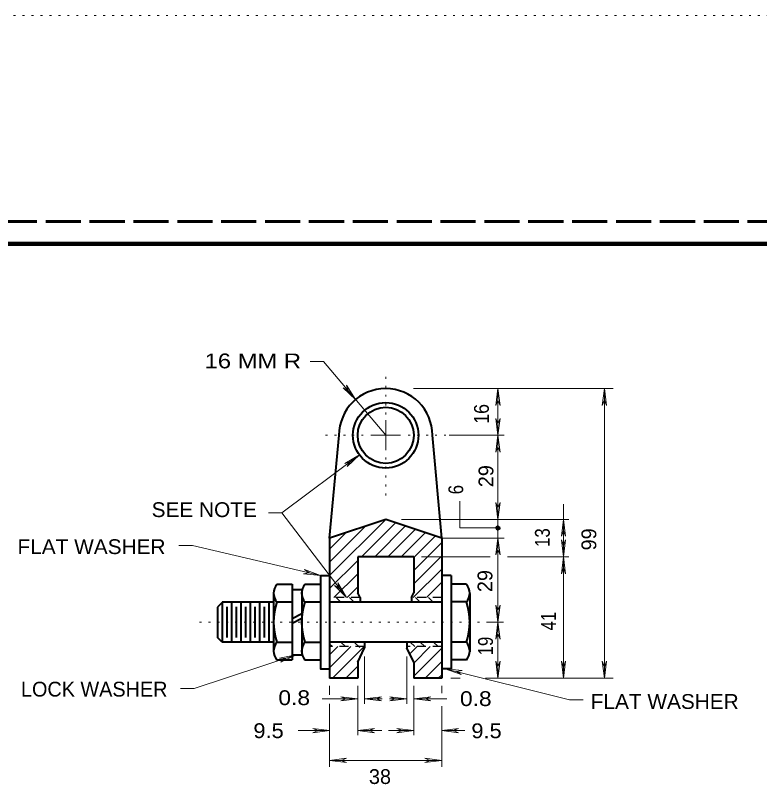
# Model space of a CAD drawing. Extents: x 312583 to 312854, y 144419 to 144597.
# Drawn here: x 312686.4 to 312724.55, y 144556.8 to 144596.78 of the extents above; entities that cross this region are included whole.
import ezdxf

# ---------------------------------------------------------------- set-up
doc = ezdxf.new("R2010")
doc.units = 0
doc.header["$LTSCALE"] = 0.3
for name, pattern in [('DOTTED', [1.5, 0.3, -1.2]), ('LONG_DASHED', [7.5, 6, -1.5]), ('SHORT_DASHED', [2.7, 1.5, -1.2])]:
    doc.linetypes.add(name, pattern=pattern)
for name, color, linetype, lineweight in [('1', 7, 'Continuous', 40), ('2', 7, 'Continuous', 13), ('62', 7, 'DOTTED', 13), ('63', 7, 'LONG_DASHED', 60)]:
    doc.layers.add(name, color=color, linetype=linetype, lineweight=lineweight)

msp = doc.modelspace()

# ---------------------------------------------------------------- linework, layer by layer
at = {"layer": '1'}
for p, q in [((312702.5116, 144569.9919), (312702.9946, 144575.2666)), ((312708.2616, 144569.9919), (312707.7863, 144575.2666)), ((312702.5116, 144569.9919), (312702.5116, 144562.8082)), ((312708.2616, 144569.9919), (312708.2616, 144562.8082)), ((312703.953, 144569.0336), (312703.953, 144567.1782)), ((312706.828, 144569.0336), (312703.953, 144569.0336)), ((312706.828, 144569.0336), (312706.828, 144567.1782)), ((312702.0363, 144568.0752), (312702.5116, 144568.0752)), ((312708.7446, 144568.0752), (312708.2616, 144568.0752)), ((312699.8053, 144567.6306), (312700.595, 144567.6306)), ((312700.595, 144567.6306), (312700.595, 144563.7436)), ((312701.239, 144567.6306), (312702.0363, 144567.6306)), ((312709.5343, 144567.6306), (312708.7446, 144567.6306)), ((312699.6366, 144567.1476), (312699.6366, 144564.1576)), ((312699.6366, 144567.1476), (312699.6366, 144564.1652)), ((312700.595, 144567.3546), (312701.078, 144567.3546)), ((312701.078, 144567.3546), (312701.078, 144564.0042)), ((312701.078, 144567.1476), (312701.078, 144564.1652)), ((312704.068, 144566.9406), (312703.953, 144567.1782)), ((312706.7053, 144566.9406), (312706.828, 144567.1782)), ((312709.703, 144567.1476), (312709.703, 144564.1652)), ((312696.9993, 144566.6952), (312696.7616, 144566.4576)), ((312699.6366, 144566.7029), (312696.9993, 144566.7029)), ((312696.9993, 144566.7029), (312696.9993, 144564.6636)), ((312697.4823, 144566.7029), (312697.4823, 144564.6636)), ((312697.9576, 144566.7029), (312697.9576, 144564.6636)), ((312698.4406, 144566.7029), (312698.4406, 144564.6636)), ((312698.916, 144566.7029), (312698.916, 144564.6636)), ((312699.399, 144566.7029), (312699.399, 144564.6636)), ((312699.8053, 144566.7182), (312700.595, 144566.7182)), ((312701.239, 144566.7182), (312702.0363, 144566.7182)), ((312708.2616, 144566.7029), (312702.5116, 144566.7029)), ((312704.068, 144566.9406), (312704.068, 144566.7029)), ((312706.7053, 144566.9406), (312706.7053, 144566.7029)), ((312709.5343, 144566.7182), (312708.7446, 144566.7182)), ((312696.7616, 144566.4576), (312696.7616, 144564.9012)), ((312697.237, 144566.4652), (312697.237, 144564.9012)), ((312697.72, 144566.4652), (312697.72, 144564.9012)), ((312698.1953, 144566.4652), (312698.1953, 144564.9012)), ((312698.6783, 144566.4652), (312698.6783, 144564.9012)), ((312699.1536, 144566.4652), (312699.1536, 144564.9012)), ((312701.078, 144566.1049), (312700.595, 144565.8519)), ((312701.078, 144565.8672), (312700.595, 144565.6066)), ((312696.9993, 144564.6636), (312696.7616, 144564.9012)), ((312699.6366, 144564.6636), (312696.9993, 144564.6636)), ((312699.8053, 144564.6482), (312700.595, 144564.6482)), ((312701.239, 144564.6482), (312702.0363, 144564.6482)), ((312708.2616, 144564.6636), (312702.5116, 144564.6636)), ((312704.3056, 144564.6636), (312704.3056, 144564.3646)), ((312706.4676, 144564.6636), (312706.4676, 144564.3722)), ((312709.5343, 144564.6482), (312708.7446, 144564.6482)), ((312703.953, 144563.6362), (312704.3056, 144564.3646)), ((312706.828, 144563.6362), (312706.4676, 144564.3722)), ((312700.595, 144564.0042), (312701.078, 144564.0042)), ((312699.8053, 144563.7436), (312700.595, 144563.7436)), ((312701.239, 144563.7436), (312702.0363, 144563.7436)), ((312703.953, 144563.6362), (312703.953, 144562.8082)), ((312706.828, 144563.6362), (312706.828, 144562.8082)), ((312709.5343, 144563.7436), (312708.7446, 144563.7436)), ((312703.953, 144562.8082), (312702.5116, 144562.8082)), ((312708.2616, 144562.8082), (312706.828, 144562.8082))]:
    msp.add_line(p, q, dxfattribs=at)
at = {"layer": '1', "linetype": 'SHORT_DASHED', "lineweight": 25}
for p, q in [((312704.068, 144566.9406), (312702.5116, 144566.9406)), ((312708.2616, 144566.9406), (312706.7053, 144566.9406)), ((312704.2826, 144564.4259), (312702.5116, 144564.4259)), ((312708.2616, 144564.4259), (312706.4676, 144564.4259))]:
    msp.add_line(p, q, dxfattribs=at)
at = {"layer": '1', "linetype": 'DOTTED', "lineweight": 13}
msp.add_line((312710.6536, 144565.6832), (312695.7956, 144565.6832), dxfattribs=at)
at = {"layer": '1', "lineweight": 158}
msp.add_lwpolyline([(312616.5, 144423.1446), (312616.5, 144585.0846), (312849, 144585.0846)], dxfattribs=at)
at = {"layer": '1'}
for points in [[(312708.2616, 144569.9919), (312705.3866, 144570.9502), (312702.5116, 144569.9919)], [(312702.0363, 144568.0752), (312702.0363, 144563.2836), (312702.5116, 144563.2836)], [(312708.7446, 144568.0752), (312708.7446, 144563.2836), (312708.2616, 144563.2836)]]:
    msp.add_lwpolyline(points, dxfattribs=at)
for radius in [1.679, 1.4375]:
    msp.add_circle((312705.3866, 144575.2627), radius, dxfattribs=at)
for centre, radius, start, end in [((312705.3866, 144575.2627), 2.3958, 0, 180), ((312700.3449, 144567.1648), 0.7083, 140.10625, 219.89375), ((312701.7824, 144567.1648), 0.7083, 140.10625, 219.89375), ((312708.9909, 144567.1648), 0.7083, 320.10625, 39.89375), ((312702.9684, 144565.6832), 3.3318, 161.90198, 198.09802), ((312704.4059, 144565.6832), 3.3318, 161.90198, 198.09802), ((312706.3673, 144565.6832), 3.3318, 341.90198, 18.09802), ((312700.3449, 144564.194), 0.7083, 140.10625, 219.89375), ((312701.7824, 144564.194), 0.7083, 140.10625, 219.89375), ((312708.9909, 144564.194), 0.7083, 320.10625, 39.89375)]:
    msp.add_arc(centre, radius, start, end, dxfattribs=at)
at = {"layer": '2'}
for p, q in [((312702.1973, 144579.0462), (312701.5073, 144579.0462)), ((312705.3866, 144575.2666), (312702.1973, 144579.0462)), ((312703.3703, 144577.8272), (312703.4623, 144577.5436)), ((312703.8456, 144577.0912), (312703.3703, 144577.8272)), ((312703.2016, 144577.6892), (312703.4623, 144577.5436)), ((312703.8456, 144577.0912), (312703.2016, 144577.6892)), ((312706.8203, 144577.6586), (312717.0476, 144577.6586)), ((312711.1443, 144577.6586), (312711.037, 144576.7922)), ((312711.1443, 144577.6586), (312711.2516, 144576.7922)), ((312716.603, 144577.6586), (312716.4956, 144576.7922)), ((312716.603, 144577.6586), (312716.603, 144562.8082)), ((312716.603, 144577.6586), (312716.7103, 144576.7922)), ((312711.037, 144576.7922), (312711.1443, 144577.0682)), ((312711.2516, 144576.7922), (312711.1443, 144577.0682)), ((312716.4956, 144576.7922), (312716.603, 144577.0682)), ((312716.7103, 144576.7922), (312716.603, 144577.0682)), ((312705.3866, 144575.2666), (312705.3866, 144576.0332)), ((312711.037, 144576.1329), (312711.1443, 144575.8569)), ((312711.1443, 144575.2666), (312711.037, 144576.1329)), ((312711.2516, 144576.1329), (312711.1443, 144575.8569)), ((312711.1443, 144575.2666), (312711.2516, 144576.1329)), ((312705.3866, 144575.2666), (312704.62, 144575.2666)), ((312705.3866, 144575.2666), (312705.3866, 144574.4999)), ((312705.3866, 144575.2666), (312706.1533, 144575.2666)), ((312708.6373, 144575.2666), (312711.4586, 144575.2666)), ((312711.1443, 144575.2666), (312711.037, 144574.4002)), ((312711.1443, 144575.2666), (312711.2516, 144574.4002)), ((312711.037, 144574.4002), (312711.1443, 144574.6762)), ((312711.2516, 144574.4002), (312711.1443, 144574.6762)), ((312704.045, 144574.2622), (312703.286, 144573.8252)), ((312704.045, 144574.2622), (312703.4163, 144573.6566)), ((312703.286, 144573.8252), (312703.5696, 144573.9096)), ((312703.4163, 144573.6566), (312703.5696, 144573.9096)), ((312711.037, 144571.8166), (312711.1443, 144571.5406)), ((312711.1443, 144570.9502), (312711.037, 144571.8166)), ((312711.2516, 144571.8166), (312711.1443, 144571.5406)), ((312711.1443, 144570.9502), (312711.2516, 144571.8166)), ((312700.0583, 144571.2799), (312699.3683, 144571.2799)), ((312705.3866, 144570.9502), (312702.5116, 144568.0752)), ((312704.367, 144570.6129), (312702.5116, 144568.7576)), ((312705.8926, 144570.7816), (312704.1446, 144569.0336)), ((312706.4063, 144570.6129), (312704.827, 144569.0336)), ((312706.1916, 144570.9502), (312714.7706, 144570.9502)), ((312714.5023, 144570.9502), (312714.395, 144570.0839)), ((312714.5023, 144570.9502), (312714.6096, 144570.0839)), ((312703.355, 144570.2756), (312702.5116, 144569.4322)), ((312706.9123, 144570.4442), (312705.5016, 144569.0336)), ((312707.426, 144570.2756), (312706.184, 144569.0336)), ((312714.395, 144570.0839), (312714.5023, 144570.3599)), ((312714.6096, 144570.0839), (312714.5023, 144570.3599)), ((312707.932, 144570.1069), (312706.828, 144569.0029)), ((312708.2616, 144569.9919), (312711.4586, 144569.9919)), ((312711.1443, 144569.9919), (312711.037, 144569.1256)), ((312711.1443, 144569.9919), (312711.2516, 144569.1256)), ((312714.395, 144569.8999), (312714.5023, 144569.6239)), ((312714.5023, 144569.0336), (312714.395, 144569.8999)), ((312714.6096, 144569.8999), (312714.5023, 144569.6239)), ((312714.5023, 144569.0336), (312714.6096, 144569.8999)), ((312695.4736, 144569.6162), (312694.7836, 144569.6162)), ((312702.0363, 144568.0752), (312695.4736, 144569.6162)), ((312708.2616, 144569.7619), (312706.828, 144568.3282)), ((312711.037, 144569.1256), (312711.1443, 144569.4016)), ((312711.2516, 144569.1256), (312711.1443, 144569.4016)), ((312708.2616, 144569.0872), (312706.828, 144567.6536)), ((312707.2266, 144569.0336), (312710.738, 144569.0336)), ((312711.635, 144569.0336), (312714.7706, 144569.0336)), ((312714.5023, 144569.0336), (312714.395, 144568.1672)), ((312714.5023, 144569.0336), (312714.6096, 144568.1672)), ((312703.953, 144568.8419), (312702.5116, 144567.4006)), ((312701.17, 144568.1672), (312701.4613, 144568.2132)), ((312701.216, 144568.3819), (312701.4613, 144568.2132)), ((312702.0363, 144568.0752), (312701.216, 144568.3819)), ((312708.2616, 144568.4049), (312706.7973, 144566.9406)), ((312714.395, 144568.1672), (312714.5023, 144568.4432)), ((312714.6096, 144568.1672), (312714.5023, 144568.4432)), ((312702.0363, 144568.0752), (312701.17, 144568.1672)), ((312702.734, 144566.9406), (312703.953, 144568.1596)), ((312702.757, 144567.5692), (312703.01, 144567.4082)), ((312703.3703, 144566.9406), (312702.757, 144567.5692)), ((312702.9256, 144567.6996), (312703.01, 144567.4082)), ((312703.3703, 144566.9406), (312702.9256, 144567.6996)), ((312703.953, 144567.4849), (312703.4086, 144566.9406)), ((312708.2616, 144567.7302), (312707.472, 144566.9406)), ((312702.8413, 144566.9406), (312703.079, 144566.7029)), ((312703.5236, 144566.9406), (312703.7613, 144566.7029)), ((312706.9123, 144566.9406), (312707.15, 144566.7029)), ((312707.587, 144566.9406), (312707.8246, 144566.7029)), ((312711.037, 144566.5496), (312711.1443, 144566.2736)), ((312711.1443, 144565.6832), (312711.037, 144566.5496)), ((312711.2516, 144566.5496), (312711.1443, 144566.2736)), ((312711.1443, 144565.6832), (312711.2516, 144566.5496)), ((312710.6536, 144565.6832), (312711.428, 144565.6832)), ((312711.1443, 144565.6832), (312711.037, 144564.8169)), ((312711.1443, 144565.6832), (312711.2516, 144564.8169)), ((312711.037, 144564.8169), (312711.1443, 144565.0929)), ((312711.2516, 144564.8169), (312711.1443, 144565.0929)), ((312703.0866, 144564.6636), (312703.3243, 144564.4259)), ((312703.769, 144564.6636), (312704.0526, 144564.3799)), ((312706.874, 144564.4259), (312706.6363, 144564.6636)), ((312707.1576, 144564.6636), (312707.3953, 144564.4259)), ((312707.8323, 144564.6636), (312708.07, 144564.4259)), ((312702.5116, 144564.5639), (312702.6496, 144564.4259)), ((312702.9256, 144564.4259), (312702.5116, 144564.0119)), ((312703.6003, 144564.4259), (312702.5116, 144563.3372)), ((312704.3056, 144564.4489), (312702.665, 144562.8082)), ((312706.9966, 144564.4259), (312706.621, 144564.0502)), ((312707.6713, 144564.4259), (312706.828, 144563.5826)), ((312708.2616, 144564.3416), (312706.828, 144562.9079)), ((312700.802, 144564.0042), (312695.558, 144562.2792)), ((312700.802, 144564.0042), (312699.9433, 144563.8356)), ((312699.9433, 144563.8356), (312700.2423, 144563.8202)), ((312700.802, 144564.0042), (312700.0123, 144563.6286)), ((312700.0123, 144563.6286), (312700.2423, 144563.8202)), ((312704.3056, 144563.9276), (312704.3056, 144561.4896)), ((312706.4676, 144563.9276), (312706.4676, 144561.4972)), ((312703.953, 144563.4216), (312703.3396, 144562.8082)), ((312708.2616, 144563.6669), (312707.403, 144562.8082)), ((312711.037, 144563.6746), (312711.1443, 144563.3986)), ((312711.1443, 144562.8082), (312711.037, 144563.6746)), ((312711.2516, 144563.6746), (312711.1443, 144563.3986)), ((312711.1443, 144562.8082), (312711.2516, 144563.6746)), ((312714.395, 144563.6746), (312714.5023, 144563.3986)), ((312714.5023, 144562.8082), (312714.395, 144563.6746)), ((312714.6096, 144563.6746), (312714.5023, 144563.3986)), ((312714.5023, 144562.8082), (312714.6096, 144563.6746)), ((312716.4956, 144563.6746), (312716.603, 144563.3986)), ((312716.603, 144562.8082), (312716.4956, 144563.6746)), ((312716.7103, 144563.6746), (312716.603, 144563.3986)), ((312716.603, 144562.8082), (312716.7103, 144563.6746)), ((312708.438, 144563.2836), (312714.8166, 144561.6966)), ((312708.438, 144563.2836), (312709.2583, 144562.9922)), ((312708.438, 144563.2836), (312709.3043, 144563.2069)), ((312709.3043, 144563.2069), (312709.013, 144563.1532)), ((312709.2583, 144562.9922), (312709.013, 144563.1532)), ((312708.2616, 144562.9846), (312708.0853, 144562.8082)), ((312708.7216, 144562.8082), (312709.2123, 144562.8082)), ((312710.508, 144562.8082), (312717.0476, 144562.8082)), ((312695.558, 144562.2792), (312694.868, 144562.2792)), ((312702.5116, 144562.4172), (312702.5116, 144561.9496)), ((312703.953, 144562.4172), (312703.953, 144559.8796)), ((312706.828, 144562.4172), (312706.828, 144559.8796)), ((312708.2616, 144562.4172), (312708.2616, 144562.0416)), ((312703.0866, 144561.8576), (312703.3626, 144561.7502)), ((312703.953, 144561.7502), (312703.0866, 144561.8576)), ((312704.3056, 144561.7502), (312705.172, 144561.8576)), ((312705.172, 144561.8576), (312704.896, 144561.7502)), ((312705.6013, 144561.8576), (312705.8773, 144561.7502)), ((312706.4676, 144561.7502), (312705.6013, 144561.8576)), ((312706.828, 144561.7502), (312707.6943, 144561.8576)), ((312707.6943, 144561.8576), (312707.4183, 144561.7502)), ((312702.1283, 144561.7502), (312703.953, 144561.7502)), ((312702.5116, 144561.4896), (312702.5116, 144558.2696)), ((312703.0866, 144561.6429), (312703.3626, 144561.7502)), ((312703.953, 144561.7502), (312703.0866, 144561.6429)), ((312704.3056, 144561.7502), (312705.2103, 144561.7502)), ((312704.3056, 144561.7502), (312705.172, 144561.6429)), ((312705.172, 144561.6429), (312704.896, 144561.7502)), ((312705.586, 144561.7502), (312706.4676, 144561.7502)), ((312705.6013, 144561.6429), (312705.8773, 144561.7502)), ((312706.4676, 144561.7502), (312705.6013, 144561.6429)), ((312706.828, 144561.7502), (312708.5223, 144561.7502)), ((312706.828, 144561.7502), (312707.6943, 144561.6429)), ((312707.6943, 144561.6429), (312707.4183, 144561.7502)), ((312715.5066, 144561.6966), (312714.8166, 144561.6966)), ((312708.2616, 144561.3746), (312708.2616, 144558.2696)), ((312701.6453, 144560.2246), (312701.9213, 144560.1172)), ((312702.5116, 144560.1172), (312701.6453, 144560.2246)), ((312703.953, 144560.1172), (312704.8193, 144560.2246)), ((312704.8193, 144560.2246), (312704.5433, 144560.1172)), ((312705.9616, 144560.2246), (312706.2376, 144560.1172)), ((312706.828, 144560.1172), (312705.9616, 144560.2246)), ((312708.2616, 144560.1172), (312709.128, 144560.2246)), ((312709.128, 144560.2246), (312708.852, 144560.1172)), ((312700.894, 144560.1172), (312702.5116, 144560.1172)), ((312701.6453, 144560.0099), (312701.9213, 144560.1172)), ((312702.5116, 144560.1172), (312701.6453, 144560.0099)), ((312703.953, 144560.1172), (312705.1796, 144560.1172)), ((312703.953, 144560.1172), (312704.8193, 144560.0099)), ((312704.8193, 144560.0099), (312704.5433, 144560.1172)), ((312705.5246, 144560.1172), (312706.828, 144560.1172)), ((312705.9616, 144560.0099), (312706.2376, 144560.1172)), ((312706.828, 144560.1172), (312705.9616, 144560.0099)), ((312708.2616, 144560.1172), (312709.45, 144560.1172)), ((312708.2616, 144560.1172), (312709.128, 144560.0099)), ((312709.128, 144560.0099), (312708.852, 144560.1172)), ((312702.5116, 144558.5916), (312703.378, 144558.6989)), ((312703.378, 144558.6989), (312703.102, 144558.5916)), ((312707.3953, 144558.6989), (312707.6713, 144558.5916)), ((312708.2616, 144558.5916), (312707.3953, 144558.6989)), ((312702.5116, 144558.5916), (312708.2616, 144558.5916)), ((312702.5116, 144558.5916), (312703.378, 144558.4842)), ((312703.378, 144558.4842), (312703.102, 144558.5916)), ((312707.3953, 144558.4842), (312707.6713, 144558.5916)), ((312708.2616, 144558.5916), (312707.3953, 144558.4842))]:
    msp.add_line(p, q, dxfattribs=at)
at = {"layer": '2', "linetype": 'DOTTED'}
for p, q in [((312705.3866, 144576.3246), (312705.3866, 144578.5096)), ((312704.2366, 144575.2666), (312702.0976, 144575.2666)), ((312706.5366, 144575.2666), (312708.6373, 144575.2666)), ((312705.3866, 144574.1166), (312705.3866, 144572.1769))]:
    msp.add_line(p, q, dxfattribs=at)
at = {"layer": '2'}
for points in [[(312711.1443, 144577.6586), (312711.1443, 144575.2666), (312711.1443, 144570.9502)], [(312703.3703, 144566.9406), (312700.0583, 144571.2799), (312704.045, 144574.2622)], [(312711.1443, 144570.5132), (312709.1935, 144570.5132), (312709.1935, 144571.8932)], [(312714.5023, 144571.7399), (312714.5023, 144569.0336), (312714.5023, 144562.8082)], [(312711.1443, 144570.9502), (312711.1443, 144565.6832), (312711.1443, 144562.8082)]]:
    msp.add_lwpolyline(points, dxfattribs=at)
at = {"layer": '2', "lineweight": 40}
for radius in [0.0885, 0.0442]:
    msp.add_circle((312711.1405, 144570.5094), radius, dxfattribs=at)
at = {"layer": '62'}
msp.add_line((312601.2, 144596.7846), (312853.5, 144596.7846), dxfattribs=at)
at = {"layer": '63'}
msp.add_line((312851.75, 144586.2246), (312583.526, 144586.2246), dxfattribs=at)

# ---------------------------------------------------------------- texts
at = {"layer": '2'}
for s, width, p in [('16 MM R', 1.2, (312696.0976, 144578.6964)), ('SEE NOTE', 1.05, (312693.3818, 144571.0701)), ('FLAT WASHER', 1.05, (312686.5024, 144569.1725)), ('0.8', 1.15, (312699.8812, 144561.4272)), ('0.8', 1.15, (312709.195, 144561.3794)), ('FLAT WASHER', 1.05, (312715.9024, 144561.2328)), ('9.5', 1.1, (312698.6013, 144559.7358)), ('9.5', 1.1, (312709.7801, 144559.731))]:
    msp.add_text(s, height=0.76, dxfattribs=dict(at, width=width)).set_placement(p)
for s, width, p in [('16', 0.9, (312710.6774, 144575.8505)), ('6', 0.85, (312709.3602, 144572.236)), ('13', 0.85, (312713.8008, 144569.537)), ('41', 0.85, (312714.1157, 144565.2545)), ('19', 0.85, (312710.8854, 144563.9745))]:
    msp.add_text(s, height=0.76, rotation=90, dxfattribs=dict(at, width=width)).set_placement(p)
for s, p in [('29', (312710.9089, 144572.6019)), ('99', (312716.1867, 144569.3616)), ('29', (312710.8574, 144567.2225))]:
    msp.add_text(s, height=0.76, rotation=90, dxfattribs=at).set_placement(p)
for s, p in [('LOCK WASHER', (312686.6808, 144561.8662)), ('38', (312704.5266, 144557.3832))]:
    msp.add_text(s, height=0.76, dxfattribs=at).set_placement(p)

doc.saveas('drawing.dxf')
